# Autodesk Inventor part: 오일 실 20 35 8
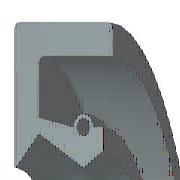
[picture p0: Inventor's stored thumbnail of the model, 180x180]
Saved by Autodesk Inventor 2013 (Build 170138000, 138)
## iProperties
Created: 2012-02
Part Number: 오일 실 20 35 8
Material: 고무
Description: 오일-실
Document SubType Name: Modeling
Standard: KS B 2804
Designer: mduedu
Standards Organization: KS
Language: ko-KR
Size Designation: D - 20 35 8
Categories: <MemberInstance><Categories><Category DisplayName="샤프트 부품" InternalName="7f7aeb1f-a693-4053-b835-cee3144e0d98" Mnemonic="SHFT"><Category DisplayName="실링" Intern
Density: 0.93 g/cm^3
IsCustomPart: 1
Author: mduedu
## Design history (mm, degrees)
revolve "본체" stored, may be unused: angle "d17" = 90 deg
revolve "스프링1" stored, may be unused: angle "d18" = 90 deg
body "Solid1"
sketch "스케치1"
  geometry: L1 (0, 17.5)-(8, 17.5); L2 (8, 15.75)-(1.75, 15.75); L3 (1.75, 11.75)-(4.9, 10); L4 (4.9, 10)-(0, 10); L5 (0, 0)-(9.586, 0) reference; L6 (4.9, 10)-(6.3, 10.875); L7 (0, 18)-(0, -3) reference; L8 (-1.941, 0)-(11.507, 0) reference; L9 (4.2, 12.1)-(1.75, 12.71); L10 (1.75, 12.71)-(1.75, 15.75); L11 (0, 17.5)-(0, 10.088); L12 (4.9, 10)-(0, 10); L13 (1.75, 11.75)-(0.152, 10.028); L14 (8, 17.5)-(8, 15.75); L15 (5.6, 12.1)-(6.3, 12.1); L16 (6.3, 12.1)-(6.3, 10.875); C1 r 0.455 at (4.9, 12.1); A1 r 0.7 centre (4.9, 12.1) between (5.6, 12.1) and (4.2, 12.1); A2 r 0.088 centre (0.088, 10.088) between (0, 10.088) and (0.152, 10.028); 1 further point
  constraints: 28 end point, 5 horizontal alignment, 5 point on line, 4 point on circle, 4 vertical alignment, 3 centre point, 3 tangent, 2 collinear, 2 horizontal, 2 perpendicular, 1 coincident, 1 parallel
  dimensions: "d0" = 35 diameter of L1 L5 (= SD2); "d1" = 1.75 distance of L1.end L2.start (= SD); "d2" = 0.91 diameter of C1 (= SPDI); "d3" = 1.4 diameter of A1 (= SPDA); "d4" = 20 diameter of L3.end L5 (= NND); "d5" = 23.5 diameter of L3.start L5 (= TKDM); "d7" = 25.42 diameter of L9.end L5 (= TKDM + 0.24 x SWDT); "d8" = 1.75 distance between parallel lines of L11 L10 (= SD); "d9" = 4.9 distance from line of L11 C1.centre (= SPDST); "d10" = 24.2 diameter of C1.centre L5 (= HLDM); "d11" = 0.0875 radius of A2 (= 0.25 x LAB); "d12" = 6.3 distance between parallel lines of L11 L16 (= SDI); "d13" = 21.75 diameter of L6.end L5 (= ABDM); "d14" = 8 distance from line of L11 L1.end (= SWDT)
fillet "모깎기1" dims "d6" = 0.3 (= RR)
other parameters: "SD2" = 35 [user parameter; used in 1 equation term], "SWDT" = 8 [user parameter; used in 2 equation terms], "RR" = 0.3 [user parameter; used in 1 equation term], "SD" = 1.75 [user parameter; used in 2 equation terms], "NND" = 20 [user parameter; used in 1 equation term], "SPDA" = 1.4 [user parameter; used in 1 equation term], "SPDI" = 0.91 [user parameter; used in 1 equation term], "TKDM" = 23.5 [user parameter; used in 2 equation terms], "HLDM" = 24.2 [user parameter; used in 1 equation term], "ABDM" = 21.75 [user parameter; used in 1 equation term], "SDI" = 6.3 [user parameter; used in 1 equation term], "SPDST" = 4.9 [user parameter; used in 1 equation term], "LAB" = 0.35 [user parameter; used in 1 equation term], "d15" = 0, "d16" = 0, "d19" = 0
